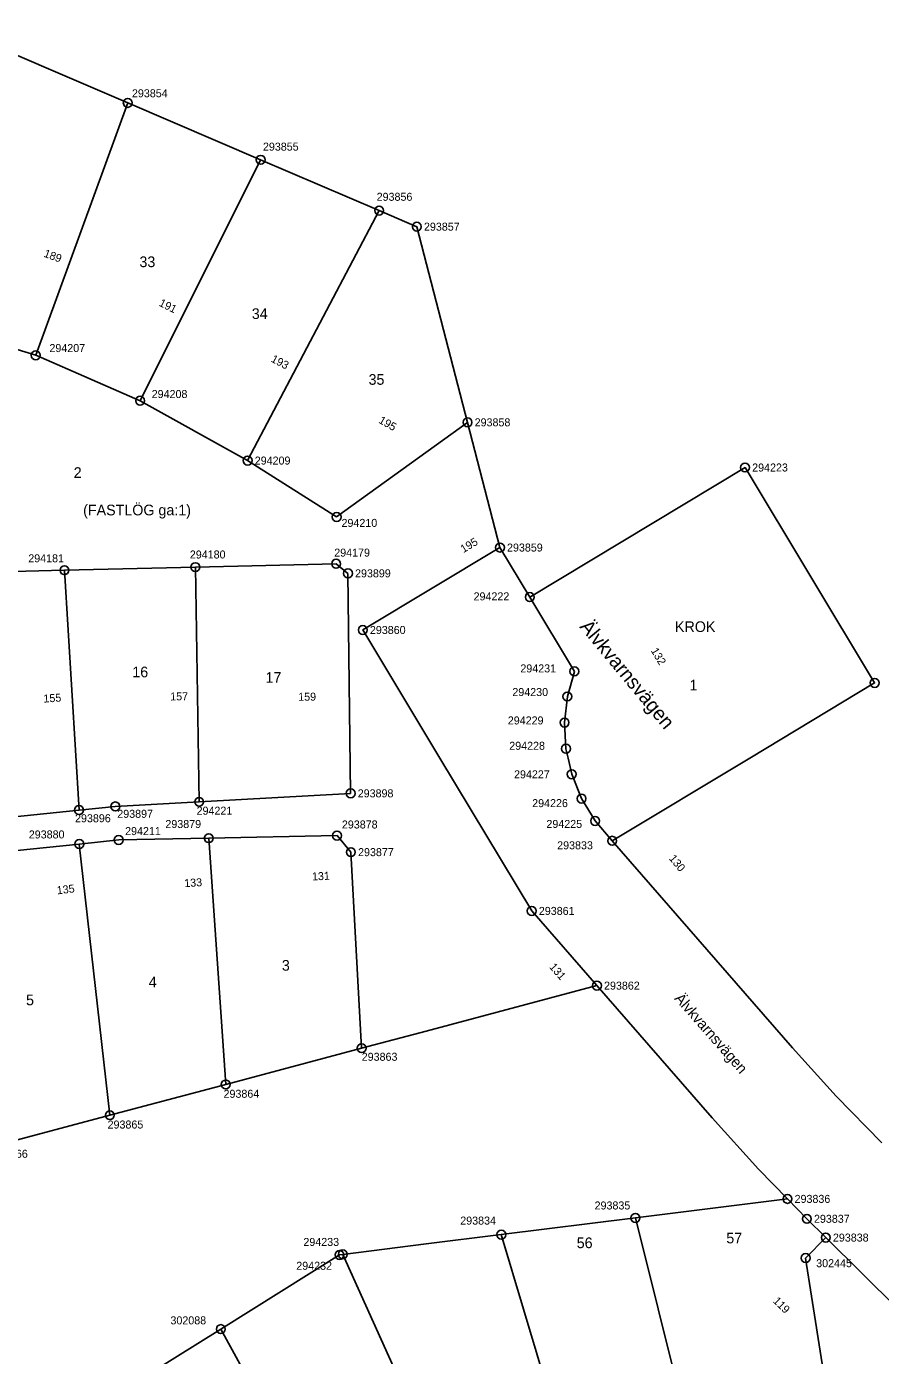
# Model space of a CAD drawing. Extents: x 141995 to 152570, y 6580184 to 6586000.
# Drawn here: x 142694.8 to 142790.9, y 6585633.6 to 6585783 of the extents above; entities that cross this region are included whole.
import ezdxf

# ---------------------------------------------------------------- set-up
doc = ezdxf.new("R2010")
doc.units = 0
for name, color, linetype in [('Level 10', 7, 'Continuous'), ('Level 13', 7, 'Continuous'), ('Level 42', 7, 'Continuous'), ('Level 43', 7, 'Continuous'), ('Level 5', 7, 'Continuous'), ('Level 50', 7, 'Continuous'), ('Level 51', 7, 'Continuous'), ('Level 53', 7, 'Continuous'), ('Level 54', 7, 'Continuous'), ('Level 55', 7, 'Continuous'), ('Level 59', 7, 'Continuous'), ('Level 6', 7, 'Continuous'), ('Level 7', 7, 'Continuous')]:
    doc.layers.add(name, color=color, linetype=linetype)

msp = doc.modelspace()

# ---------------------------------------------------------------- linework, layer by layer
at = {"layer": 'Level 10'}
for centre in [(142706.21, 6585774.43), (142721.15, 6585768.03), (142734.48, 6585762.32), (142738.72, 6585760.51), (142695.86, 6585746.05), (142707.6, 6585740.94), (142744.42, 6585738.51), (142719.69, 6585734.21), (142775.63, 6585733.43), (142729.7, 6585727.87), (142748.06, 6585724.43), (142699.09, 6585721.88), (142713.81, 6585722.23), (142729.64, 6585722.61), (142730.97, 6585721.53), (142751.42, 6585718.86), (142732.64, 6585715.16), (142756.44, 6585710.51), (142790.2, 6585709.21), (142755.65, 6585707.68), (142755.33, 6585704.75), (142755.49, 6585701.81), (142756.14, 6585698.94), (142731.27, 6585696.79), (142757.24, 6585696.2), (142700.73, 6585694.91), (142704.81, 6585695.32), (142714.24, 6585695.84), (142758.77, 6585693.69), (142705.19, 6585691.55), (142715.32, 6585691.75), (142729.74, 6585692.04), (142760.69, 6585691.46), (142700.76, 6585691.09), (142731.3, 6585690.18), (142751.64, 6585683.57), (142758.97, 6585675.17), (142732.51, 6585668.14), (142717.23, 6585664.06), (142704.19, 6585660.6), (142780.4, 6585651.19), (142763.3, 6585649.05), (142782.58, 6585648.95), (142748.22, 6585647.17), (142784.71, 6585646.84), (142730.02, 6585644.89), (142730.39, 6585644.95), (142782.44, 6585644.54), (142716.67, 6585636.55)]:
    msp.add_circle(centre, 0.5, dxfattribs=at)
at = {"layer": 'Level 13'}
for points in [[(142748.06, 6585724.43), (142751.42, 6585718.86)], [(142760.69, 6585691.46), (142780.96, 6585668.18)], [(142758.97, 6585675.17), (142771.92, 6585660.3)], [(142780.96, 6585668.18), (142785.89, 6585662.74)], [(142785.89, 6585662.74), (142791.01, 6585657.5)], [(142771.92, 6585660.3), (142777.14, 6585654.53)], [(142777.14, 6585654.53), (142780.4, 6585651.19)]]:
    msp.add_lwpolyline(points, dxfattribs=at)
at = {"layer": 'Level 5'}
for points in [[(142686.17, 6585783.01), (142706.21, 6585774.43)], [(142706.21, 6585774.43), (142721.15, 6585768.03)], [(142721.15, 6585768.03), (142734.48, 6585762.32)], [(142734.48, 6585762.32), (142738.72, 6585760.51)], [(142738.72, 6585760.51), (142744.42, 6585738.51)], [(142744.42, 6585738.51), (142748.06, 6585724.43)], [(142751.42, 6585718.86), (142775.63, 6585733.43)], [(142775.63, 6585733.43), (142790.2, 6585709.21)], [(142748.06, 6585724.43), (142732.64, 6585715.16)], [(142756.44, 6585710.51), (142751.42, 6585718.86)], [(142732.64, 6585715.16), (142741.32, 6585700.73)], [(142755.65, 6585707.68), (142756.44, 6585710.51)], [(142790.2, 6585709.21), (142776.16, 6585700.76)], [(142755.33, 6585704.75), (142755.65, 6585707.68)], [(142755.49, 6585701.81), (142755.33, 6585704.75)], [(142755.73, 6585700.75), (142755.49, 6585701.81)], [(142741.32, 6585700.73), (142751.64, 6585683.57)], [(142756.14, 6585698.94), (142755.73, 6585700.75)], [(142776.16, 6585700.76), (142760.69, 6585691.46)], [(142757.24, 6585696.2), (142756.14, 6585698.94)], [(142758.77, 6585693.69), (142757.24, 6585696.2)], [(142760.69, 6585691.46), (142758.77, 6585693.69)], [(142751.64, 6585683.57), (142758.97, 6585675.17)], [(142758.97, 6585675.17), (142739.75, 6585670.06)], [(142739.75, 6585670.06), (142732.51, 6585668.14)], [(142732.51, 6585668.14), (142717.23, 6585664.06)], [(142717.23, 6585664.06), (142704.19, 6585660.6)], [(142704.19, 6585660.6), (142691.52, 6585657.23)], [(142763.3, 6585649.05), (142780.4, 6585651.19)], [(142780.4, 6585651.19), (142782.58, 6585648.95)], [(142748.22, 6585647.17), (142763.3, 6585649.05)], [(142782.58, 6585648.95), (142784.71, 6585646.84)], [(142739.77, 6585646.12), (142748.22, 6585647.17)], [(142730.39, 6585644.95), (142739.77, 6585646.12)], [(142784.71, 6585646.84), (142792.82, 6585638.84)], [(142716.67, 6585636.55), (142730.02, 6585644.89)], [(142730.02, 6585644.89), (142730.39, 6585644.95)], [(142704.06, 6585628.67), (142716.67, 6585636.55)]]:
    msp.add_lwpolyline(points, dxfattribs=at)
at = {"layer": 'Level 6'}
for points in [[(142691.52, 6585657.23), (142704.19, 6585660.6), (142717.23, 6585664.06), (142732.51, 6585668.14), (142739.75, 6585670.06), (142758.97, 6585675.17), (142751.64, 6585683.57), (142741.32, 6585700.73), (142732.64, 6585715.16), (142748.06, 6585724.43), (142744.42, 6585738.51), (142738.72, 6585760.51), (142734.48, 6585762.32), (142721.15, 6585768.03), (142706.21, 6585774.43), (142686.17, 6585783.01)], [(142840.97, 6585591.35), (142792.82, 6585638.84), (142784.71, 6585646.84), (142782.58, 6585648.95), (142780.4, 6585651.19), (142763.3, 6585649.05), (142748.22, 6585647.17), (142739.77, 6585646.12), (142730.39, 6585644.95), (142730.02, 6585644.89), (142716.67, 6585636.55), (142704.06, 6585628.67)]]:
    msp.add_lwpolyline(points, dxfattribs=at)
msp.add_lwpolyline([(142751.42, 6585718.86), (142756.44, 6585710.51), (142755.65, 6585707.68), (142755.33, 6585704.75), (142755.49, 6585701.81), (142755.73, 6585700.75), (142756.14, 6585698.94), (142757.24, 6585696.2), (142758.77, 6585693.69), (142760.69, 6585691.46), (142776.16, 6585700.76), (142790.2, 6585709.21), (142775.63, 6585733.43)], close=True, dxfattribs=at)
at = {"layer": 'Level 7'}
for points in [[(142706.21, 6585774.43), (142695.86, 6585746.05)], [(142721.15, 6585768.03), (142707.6, 6585740.94)], [(142734.48, 6585762.32), (142719.69, 6585734.21)], [(142677.93, 6585751.5), (142695.86, 6585746.05)], [(142695.86, 6585746.05), (142707.6, 6585740.94)], [(142707.6, 6585740.94), (142719.69, 6585734.21)], [(142729.7, 6585727.87), (142744.42, 6585738.51)], [(142719.69, 6585734.21), (142729.7, 6585727.87)], [(142699.09, 6585721.88), (142684.56, 6585721.53)], [(142713.81, 6585722.23), (142699.09, 6585721.88)], [(142699.09, 6585721.88), (142700.73, 6585694.91)], [(142729.64, 6585722.61), (142713.81, 6585722.23)], [(142713.81, 6585722.23), (142714.24, 6585695.84)], [(142730.97, 6585721.53), (142729.64, 6585722.61)], [(142731.27, 6585696.79), (142730.97, 6585721.53)], [(142714.24, 6585695.84), (142731.27, 6585696.79)], [(142700.73, 6585694.91), (142704.81, 6585695.32)], [(142704.81, 6585695.32), (142714.24, 6585695.84)], [(142689.44, 6585693.75), (142700.73, 6585694.91)], [(142729.74, 6585692.04), (142715.32, 6585691.75)], [(142731.3, 6585690.18), (142729.74, 6585692.04)], [(142700.76, 6585691.09), (142690.07, 6585690)], [(142705.19, 6585691.55), (142700.76, 6585691.09)], [(142704.19, 6585660.6), (142700.76, 6585691.09)], [(142715.32, 6585691.75), (142705.19, 6585691.55)], [(142717.23, 6585664.06), (142715.32, 6585691.75)], [(142732.51, 6585668.14), (142731.3, 6585690.18)], [(142763.3, 6585649.05), (142765.85, 6585638.82)], [(142748.22, 6585647.17), (142750.72, 6585638.8)], [(142784.71, 6585646.84), (142782.44, 6585644.54)], [(142730.39, 6585644.95), (142746.26, 6585609.78)], [(142783.34, 6585638.83), (142782.44, 6585644.54)], [(142750.72, 6585638.8), (142758.3, 6585613.49)], [(142771.28, 6585617.04), (142765.85, 6585638.82)], [(142786.33, 6585619.8), (142783.34, 6585638.83)], [(142716.67, 6585636.55), (142734.07, 6585604.78)]]:
    msp.add_lwpolyline(points, dxfattribs=at)

# ---------------------------------------------------------------- texts
at = {"layer": 'Level 42'}
msp.add_text('Älvkvarnsvägen', height=1.2, rotation=311.2991, dxfattribs=at).set_placement((142767.63, 6585673.68))
at = {"layer": 'Level 43'}
msp.add_text('Älvkvarnsvägen', height=1.6, rotation=309.6581, dxfattribs=at).set_placement((142756.96, 6585715.49))
at = {"layer": 'Level 50'}
msp.add_text('KROK', height=1.2, rotation=0.0485, dxfattribs=at).set_placement((142767.75, 6585714.93))
at = {"layer": 'Level 51'}
for s, p in [('33', (142707.52, 6585755.96)), ('34', (142720.16, 6585750.13)), ('35', (142733.29, 6585742.73)), ('2', (142700.13, 6585732.26)), ('16', (142706.72, 6585709.84)), ('17', (142721.7, 6585709.22)), ('1', (142769.39, 6585708.37)), ('3', (142723.54, 6585676.85)), ('4', (142708.57, 6585674.98)), ('5', (142694.77, 6585672.96))]:
    msp.add_text(s, height=1.2, rotation=0.0485, dxfattribs=at).set_placement(p)
msp.add_text('(FASTLÖG ga:1)', height=1.2, dxfattribs=at).set_placement((142701.19, 6585728.05))
at = {"layer": 'Level 53'}
for s, p in [('293854', (142706.68, 6585775.06)), ('293855', (142721.41, 6585769.06)), ('293856', (142734.2, 6585763.42)), ('293857', (142739.52, 6585760.06)), ('294207', (142697.4, 6585746.41)), ('294208', (142708.9, 6585741.24)), ('293858', (142745.22, 6585738.06)), ('294209', (142720.49, 6585733.76)), ('294223', (142776.43, 6585732.98)), ('294210', (142730.25, 6585726.75)), ('293859', (142748.86, 6585723.98)), ('294181', (142695.02, 6585722.77)), ('294180', (142713.19, 6585723.2)), ('294179', (142729.43, 6585723.41)), ('293899', (142731.77, 6585721.08)), ('294222', (142745.1, 6585718.49)), ('293860', (142733.44, 6585714.71)), ('294231', (142750.36, 6585710.39)), ('294230', (142749.46, 6585707.73)), ('294229', (142748.95, 6585704.54)), ('294228', (142749.11, 6585701.69)), ('294227', (142749.65, 6585698.48)), ('293898', (142732.07, 6585696.34)), ('293897', (142705.03, 6585694.04)), ('294221', (142713.95, 6585694.39)), ('294226', (142751.69, 6585695.24)), ('293896', (142700.28, 6585693.54)), ('293879', (142710.44, 6585692.89)), ('293878', (142730.29, 6585692.84)), ('294225', (142753.29, 6585692.9)), ('293880', (142695.08, 6585691.72)), ('294211', (142705.91, 6585692.1)), ('293877', (142732.11, 6585689.73)), ('293833', (142754.5, 6585690.5)), ('293861', (142752.44, 6585683.12)), ('293862', (142759.77, 6585674.72)), ('293863', (142732.52, 6585666.72)), ('293864', (142716.98, 6585662.56)), ('293865', (142703.94, 6585659.1)), ('293866', (142690.95, 6585655.81)), ('293836', (142781.2, 6585650.74)), ('293835', (142758.71, 6585650)), ('293834', (142743.6, 6585648.3)), ('293837', (142783.38, 6585648.5)), ('293838', (142785.51, 6585646.39)), ('294233', (142725.96, 6585645.9)), ('294232', (142725.16, 6585643.22)), ('302445', (142783.63, 6585643.51)), ('302088', (142711.01, 6585637.08))]:
    msp.add_text(s, height=0.9, rotation=0.0485, dxfattribs=at).set_placement(p)
at = {"layer": 'Level 54'}
for s, rotation, p in [('189', 339.9124, (142696.69, 6585757.15)), ('191', 333.4551, (142709.64, 6585751.65)), ('193', 332.1881, (142722.24, 6585745.37)), ('195', 330.201, (142734.35, 6585738.5)), ('132', 300.7324, (142765, 6585712.84)), ('155', 3.6588, (142696.75, 6585706.99)), ('157', 0.9066, (142710.99, 6585707.23)), ('159', 0.4766, (142725.38, 6585707.2)), ('130', 309.3451, (142767.02, 6585689.45)), ('131', 2.7337, (142726.95, 6585686.99)), ('135', 6.669, (142698.28, 6585685.43)), ('133', 3.5398, (142712.59, 6585686.24))]:
    msp.add_text(s, height=0.9, rotation=rotation, dxfattribs=at).set_placement(p)
at = {"layer": 'Level 55'}
for s, rotation, p in [('195', 31.0195, (142743.96, 6585723.8)), ('131', 311.0831, (142753.56, 6585677.23)), ('119', 315.391, (142778.7, 6585639.64))]:
    msp.add_text(s, height=0.9, rotation=rotation, dxfattribs=at).set_placement(p)
at = {"layer": 'Level 59'}
for s, p in [('57', (142773.52, 6585646.19)), ('56', (142756.7, 6585645.65))]:
    msp.add_text(s, height=1.2, rotation=0.0485, dxfattribs=at).set_placement(p)

doc.saveas('drawing.dxf')
